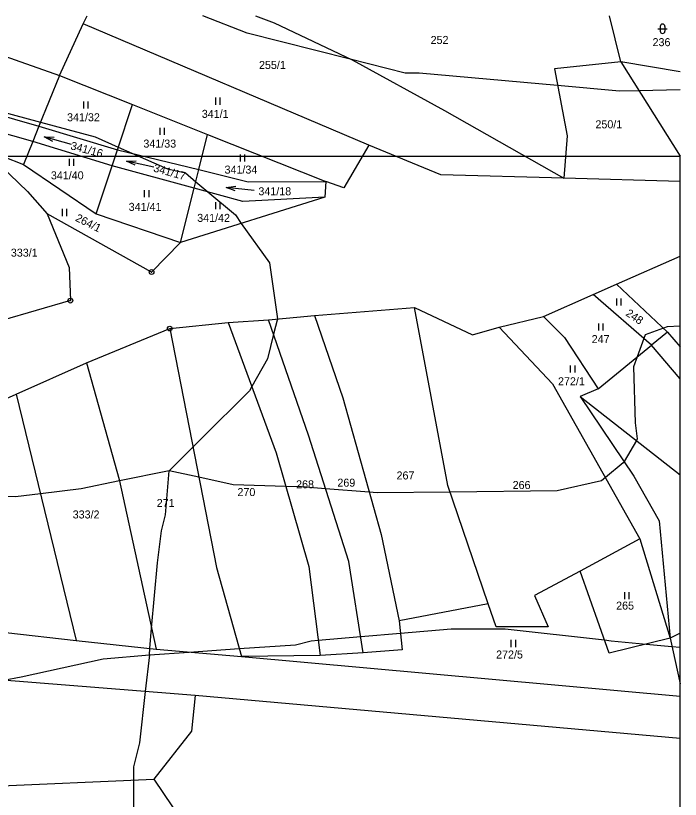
# Model space of a CAD drawing. Extents: x -756640 to -756220, y -1116060 to -1115741.
# Drawn here: x -756361.1 to -756220.1, y -1115907.5 to -1115741.2 of the extents above; entities that cross this region are included whole.
import ezdxf

# ---------------------------------------------------------------- set-up
doc = ezdxf.new("R2010")
doc.units = 0
for name, color, linetype in [('BPEJ', 7, 'Continuous'), ('Katastr_HRANICE DRÁHY', 7, 'Continuous'), ('Katastr_Hranice parcel', 7, 'Continuous'), ('Katastr_Parcelní čísla', 7, 'Continuous'), ('Katastr_Značky kultur', 7, 'Continuous')]:
    doc.layers.add(name, color=color, linetype=linetype)

msp = doc.modelspace()

# ---------------------------------------------------------------- linework, layer by layer
at = {"layer": 'BPEJ'}
for points in [[(-756220.13, -1115756.94), (-756228.88, -1115757.1), (-756233.07, -1115757.17), (-756246.16, -1115756), (-756275.51, -1115753.36), (-756278.48, -1115753.36), (-756290.19, -1115750.39), (-756312, -1115744.87), (-756321.46, -1115741.18)], [(-756364.61, -1115761.42), (-756355.88, -1115763.78), (-756344.25, -1115766.93), (-756339.39, -1115769.09), (-756336.47, -1115770.39), (-756328.97, -1115773.72), (-756325.15, -1115774.57), (-756322.94, -1115776.43), (-756320.41, -1115778.55), (-756314.54, -1115783.48), (-756313.28, -1115785.26), (-756307.33, -1115793.67), (-756305.63, -1115805.55), (-756306.45, -1115808.81), (-756307.75, -1115814.03), (-756311.06, -1115819.9), (-756311.57, -1115820.82), (-756321.76, -1115831.01), (-756323.53, -1115832.78), (-756328.55, -1115837.79)], [(-756220.13, -1115807.05), (-756222.89, -1115807.24), (-756223.7, -1115807.54), (-756227.56, -1115808.94)], [(-756227.56, -1115808.94), (-756227.86, -1115809.73), (-756229.3, -1115813.58), (-756230.1, -1115815.73), (-756229.68, -1115827.61), (-756229.26, -1115831.01), (-756229.45, -1115831.34), (-756232.07, -1115835.82), (-756232.23, -1115836.1), (-756236.03, -1115839.21), (-756236.89, -1115839.92), (-756246.23, -1115842.04), (-756268.99, -1115842.29), (-756284.42, -1115842.46), (-756286.13, -1115842.33), (-756295.38, -1115841.6), (-756300.54, -1115841.19), (-756303.81, -1115841.09), (-756314.97, -1115840.77), (-756322.27, -1115839.17), (-756328.55, -1115837.79)], [(-756328.55, -1115837.79), (-756339.1, -1115839.95), (-756347.22, -1115841.61), (-756355.89, -1115842.66)], [(-756332.79, -1115876.83), (-756332.67, -1115875.5), (-756332.3, -1115871.2), (-756331.09, -1115857.31), (-756330.24, -1115850.52), (-756329.39, -1115847.13), (-756328.55, -1115837.79)], [(-756355.89, -1115842.66), (-756361.22, -1115843.31), (-756373.35, -1115843.11), (-756382.69, -1115842.96), (-756387.1, -1115842.89), (-756391.28, -1115843.07), (-756402.93, -1115843.59), (-756415.53, -1115844.16), (-756432.93, -1115845.86), (-756441.01, -1115847.26), (-756445.2, -1115847.98), (-756454.99, -1115849.67), (-756461.04, -1115851.77), (-756475.79, -1115856.89), (-756487.39, -1115864.74), (-756490.21, -1115866.65), (-756491.4, -1115867.93), (-756498.24, -1115875.3), (-756501.24, -1115878.53)], [(-756332.79, -1115876.83), (-756324.36, -1115876.25), (-756313.7, -1115875.52), (-756301.81, -1115874.71), (-756298.42, -1115873.86), (-756296.98, -1115873.74), (-756287.94, -1115872.96), (-756279.52, -1115872.24), (-756268.72, -1115871.32), (-756257.26, -1115871.32), (-756236.21, -1115873.7), (-756234.77, -1115873.86), (-756227.37, -1115874.56), (-756221.9, -1115875.07), (-756220.13, -1115875.24)], [(-756444.19, -1115908.63), (-756440.57, -1115904.84), (-756435.47, -1115900.17), (-756422.74, -1115893.8), (-756411.29, -1115892.11), (-756409.41, -1115891.6), (-756400.26, -1115889.14), (-756381.59, -1115885.74), (-756363.76, -1115882.25), (-756359.95, -1115881.5), (-756342.55, -1115877.68), (-756332.79, -1115876.83)], [(-756332.79, -1115876.83), (-756333.68, -1115884.64), (-756334.91, -1115895.5), (-756336.18, -1115900.59), (-756336.18, -1115903.45), (-756336.18, -1115910.78), (-756335.33, -1115912.48), (-756335.76, -1115917.57), (-756331.52, -1115931.14), (-756325.58, -1115939.63), (-756314.15, -1115948.84), (-756302.4, -1115958.32), (-756299.27, -1115960.85)]]:
    msp.add_lwpolyline(points, dxfattribs=at)
at = {"layer": 'Defpoints'}
for p in [(-756640.13, -1115771.02), (-756220.13, -1116060.02)]:
    msp.add_line(p, (-756220.13, -1115771.02), dxfattribs=at)
at = {"layer": 'Katastr_HRANICE DRÁHY'}
for points in [[(-756286.21, -1115768.68), (-756291.51, -1115777.69)], [(-756270.95, -1115774.94), (-756286.21, -1115768.68)], [(-756244.82, -1115775.67), (-756270.95, -1115774.94)], [(-756295.36, -1115776.36), (-756295.53, -1115779.71)], [(-756291.51, -1115777.69), (-756295.36, -1115776.36)], [(-756220.13, -1115776.36), (-756244.82, -1115775.67)], [(-756295.53, -1115779.71), (-756326.15, -1115789.29)], [(-756332.32, -1115795.59), (-756354.5, -1115783.25)], [(-756354.5, -1115783.25), (-756349.78, -1115794.61)], [(-756326.15, -1115789.29), (-756332.32, -1115795.59)], [(-756233.67, -1115798.18), (-756220.13, -1115792.24)], [(-756349.78, -1115794.61), (-756349.55, -1115801.67)], [(-756238.65, -1115800.38), (-756233.67, -1115798.18)], [(-756349.55, -1115801.67), (-756364.06, -1115805.89)], [(-756249.19, -1115805.03), (-756238.65, -1115800.38)], [(-756297.75, -1115804.84), (-756276.55, -1115803.13)], [(-756276.55, -1115803.13), (-756264.22, -1115808.93)], [(-756307.52, -1115805.72), (-756297.75, -1115804.84)], [(-756258.54, -1115807.32), (-756249.19, -1115805.03)], [(-756328.46, -1115807.61), (-756316.08, -1115806.33)], [(-756316.08, -1115806.33), (-756307.52, -1115805.72)], [(-756346.1, -1115814.88), (-756328.46, -1115807.61)], [(-756264.22, -1115808.93), (-756258.54, -1115807.32)], [(-756361.05, -1115821.51), (-756346.1, -1115814.88)], [(-756376.92, -1115828.62), (-756361.05, -1115821.51)]]:
    msp.add_lwpolyline(points, dxfattribs=at)
at = {"layer": 'Katastr_Hranice parcel'}
for points in [[(-756346.83, -1115742.94), (-756346.01, -1115741.18)], [(-756310.26, -1115741.18), (-756306.31, -1115742.72)], [(-756232.74, -1115750.96), (-756235.15, -1115741.18)], [(-756351.86, -1115753.85), (-756346.83, -1115742.94)], [(-756286.21, -1115768.68), (-756346.83, -1115742.94)], [(-756306.31, -1115742.72), (-756289.79, -1115750.58)], [(-756370.72, -1115747.22), (-756351.86, -1115753.85)], [(-756289.79, -1115750.58), (-756270.17, -1115761.29)], [(-756232.74, -1115750.96), (-756246.82, -1115752.43)], [(-756220.13, -1115753.07), (-756232.74, -1115750.96)], [(-756232.74, -1115750.96), (-756220.13, -1115771.02)], [(-756246.82, -1115752.43), (-756244.17, -1115766.71)], [(-756351.86, -1115753.85), (-756356.23, -1115764.66)], [(-756351.86, -1115753.85), (-756336.39, -1115760)], [(-756382.59, -1115757.09), (-756356.23, -1115764.66)], [(-756339.57, -1115769.63), (-756336.39, -1115760)], [(-756336.39, -1115760), (-756320.43, -1115766.37)], [(-756357.53, -1115767.92), (-756383.55, -1115760.55)], [(-756270.17, -1115761.29), (-756244.82, -1115775.67)], [(-756356.23, -1115764.66), (-756357.53, -1115767.92)], [(-756356.23, -1115764.66), (-756339.57, -1115769.63)], [(-756322.3, -1115773.86), (-756320.43, -1115766.37)], [(-756320.43, -1115766.37), (-756295.36, -1115776.36)], [(-756244.17, -1115766.71), (-756244.82, -1115775.67)], [(-756357.53, -1115767.92), (-756359.47, -1115772.77)], [(-756340.69, -1115773.02), (-756357.53, -1115767.92)], [(-756368.19, -1115769.4), (-756358.61, -1115778.51)], [(-756368.19, -1115769.4), (-756359.47, -1115772.77)], [(-756340.69, -1115773.02), (-756339.57, -1115769.63)], [(-756339.57, -1115769.63), (-756322.3, -1115773.86)], [(-756359.47, -1115772.77), (-756344.08, -1115783.27)], [(-756344.08, -1115783.27), (-756340.69, -1115773.02)], [(-756323.28, -1115777.77), (-756340.69, -1115773.02)], [(-756323.28, -1115777.77), (-756322.3, -1115773.86)], [(-756322.3, -1115773.86), (-756311.8, -1115776.44)], [(-756311.8, -1115776.44), (-756295.36, -1115776.36)], [(-756326.15, -1115789.29), (-756323.28, -1115777.77)], [(-756312.92, -1115780.6), (-756323.28, -1115777.77)], [(-756358.61, -1115778.51), (-756354.5, -1115783.25)], [(-756295.53, -1115779.71), (-756312.92, -1115780.6)], [(-756344.08, -1115783.27), (-756326.15, -1115789.29)], [(-756233.67, -1115798.18), (-756222.85, -1115808.34)], [(-756226.28, -1115811.1), (-756238.65, -1115800.38)], [(-756269.47, -1115840.87), (-756276.55, -1115803.13)], [(-756297.75, -1115804.84), (-756291.76, -1115822.27)], [(-756249.19, -1115805.03), (-756244.72, -1115809.5)], [(-756316.08, -1115806.33), (-756305.85, -1115833.96)], [(-756299.01, -1115830.2), (-756307.52, -1115805.72)], [(-756328.46, -1115807.61), (-756318.52, -1115858.32)], [(-756258.54, -1115807.32), (-756247.22, -1115819.31)], [(-756222.85, -1115808.34), (-756226.28, -1115811.1)], [(-756222.85, -1115808.34), (-756220.13, -1115811.48)], [(-756244.72, -1115809.5), (-756237.54, -1115820.36)], [(-756237.54, -1115820.36), (-756226.28, -1115811.1)], [(-756220.13, -1115818.25), (-756226.28, -1115811.1)], [(-756346.1, -1115814.88), (-756339.17, -1115839.64)], [(-756247.22, -1115819.31), (-756228.69, -1115852.25)], [(-756361.05, -1115821.51), (-756348.29, -1115873.78)], [(-756237.54, -1115820.36), (-756241.38, -1115822.04)], [(-756291.76, -1115822.27), (-756283.6, -1115851.33)], [(-756241.38, -1115822.04), (-756229.98, -1115838.91)], [(-756241.38, -1115822.04), (-756220.13, -1115838.61)], [(-756290.46, -1115857.06), (-756299.01, -1115830.2)], [(-756305.85, -1115833.96), (-756298.96, -1115858.11)], [(-756339.17, -1115839.64), (-756331.33, -1115875.65)], [(-756229.98, -1115838.91), (-756224.63, -1115848.41)], [(-756260.9, -1115866), (-756269.47, -1115840.87)], [(-756224.63, -1115848.41), (-756222.3, -1115873.3)], [(-756283.6, -1115851.33), (-756279.8, -1115869.62)], [(-756228.69, -1115852.25), (-756241.41, -1115859.07)], [(-756228.69, -1115852.25), (-756222.3, -1115873.3)], [(-756318.52, -1115858.32), (-756313.23, -1115877.22)], [(-756298.96, -1115858.11), (-756296.57, -1115876.96)], [(-756287.4, -1115876.41), (-756290.46, -1115857.06)], [(-756241.41, -1115859.07), (-756251.09, -1115864.26)], [(-756235.22, -1115876.5), (-756241.41, -1115859.07)], [(-756251.09, -1115864.26), (-756248.17, -1115870.94)], [(-756260.9, -1115866), (-756279.8, -1115869.62)], [(-756259.21, -1115870.94), (-756260.9, -1115866)], [(-756279.8, -1115869.62), (-756279.14, -1115875.81)], [(-756248.17, -1115870.94), (-756259.21, -1115870.94)], [(-756363.21, -1115872.14), (-756348.29, -1115873.78)], [(-756220.13, -1115872.23), (-756222.3, -1115873.3)], [(-756348.29, -1115873.78), (-756331.33, -1115875.65)], [(-756222.3, -1115873.3), (-756235.22, -1115876.5)], [(-756222.3, -1115873.3), (-756220.13, -1115882.98)], [(-756331.33, -1115875.65), (-756313.23, -1115877.22)], [(-756287.4, -1115876.41), (-756296.57, -1115876.96)], [(-756279.14, -1115875.81), (-756287.4, -1115876.41)], [(-756323.04, -1115885.48), (-756423.52, -1115877.5)], [(-756296.57, -1115876.96), (-756313.23, -1115877.22)], [(-756313.23, -1115877.22), (-756220.13, -1115885.65)], [(-756323.04, -1115885.48), (-756323.86, -1115893.05)], [(-756220.13, -1115894.6), (-756323.04, -1115885.48)], [(-756323.86, -1115893.05), (-756331.81, -1115903.26)], [(-756367.5, -1115904.78), (-756331.81, -1115903.26)], [(-756331.81, -1115903.26), (-756325.96, -1115911.91)]]:
    msp.add_lwpolyline(points, dxfattribs=at)
at = {"layer": 'Katastr_Značky kultur'}
for p, q in [((-756224.41, -1115743.46), (-756224.41, -1115744.46)), ((-756223.41, -1115743.46), (-756223.41, -1115744.46)), ((-756224.91, -1115743.96), (-756222.91, -1115743.96)), ((-756346.74, -1115759.39), (-756346.74, -1115760.89)), ((-756345.74, -1115760.89), (-756345.74, -1115759.39)), ((-756318.75, -1115758.58), (-756318.75, -1115760.08)), ((-756317.75, -1115760.08), (-756317.75, -1115758.58)), ((-756330.55, -1115764.98), (-756330.55, -1115766.48)), ((-756329.55, -1115766.48), (-756329.55, -1115764.98)), ((-756349.31, -1115768.55), (-756355.07, -1115766.87)), ((-756349.82, -1115771.55), (-756349.82, -1115773.05)), ((-756348.82, -1115773.05), (-756348.82, -1115771.55)), ((-756313.5, -1115770.64), (-756313.5, -1115772.14)), ((-756312.5, -1115772.14), (-756312.5, -1115770.64)), ((-756331.81, -1115773.31), (-756337.67, -1115772.03)), ((-756333.86, -1115778.19), (-756333.86, -1115779.69)), ((-756332.86, -1115779.69), (-756332.86, -1115778.19)), ((-756310.52, -1115778.31), (-756316.48, -1115777.67)), ((-756318.77, -1115780.76), (-756318.77, -1115782.26)), ((-756317.77, -1115782.26), (-756317.77, -1115780.76)), ((-756351.31, -1115782.21), (-756351.31, -1115783.71)), ((-756350.31, -1115783.71), (-756350.31, -1115782.21)), ((-756332.37, -1115795.59), (-756332.27, -1115795.59)), ((-756349.6, -1115801.67), (-756349.5, -1115801.67)), ((-756233.65, -1115801.2), (-756233.65, -1115802.7)), ((-756232.65, -1115802.7), (-756232.65, -1115801.2)), ((-756237.51, -1115806.49), (-756237.51, -1115807.99)), ((-756236.51, -1115807.99), (-756236.51, -1115806.49)), ((-756328.51, -1115807.61), (-756328.41, -1115807.61)), ((-756243.47, -1115815.43), (-756243.47, -1115816.93)), ((-756242.47, -1115816.93), (-756242.47, -1115815.43)), ((-756231.99, -1115863.54), (-756231.99, -1115865.04)), ((-756230.99, -1115865.04), (-756230.99, -1115863.54)), ((-756256.06, -1115873.7), (-756256.06, -1115875.2)), ((-756255.06, -1115875.2), (-756255.06, -1115873.7))]:
    msp.add_line(p, q, dxfattribs=at)
for points in [[(-756353.29, -1115767.91), (-756355.07, -1115766.87), (-756353.01, -1115766.95)], [(-756335.82, -1115772.94), (-756337.67, -1115772.03), (-756335.61, -1115771.97)], [(-756314.55, -1115778.38), (-756316.48, -1115777.67), (-756314.44, -1115777.39)]]:
    msp.add_lwpolyline(points, dxfattribs=at)
for centre in [(-756332.32, -1115795.59), (-756349.55, -1115801.67), (-756328.46, -1115807.61)]:
    msp.add_circle(centre, 0.499, dxfattribs=at)
for centre, start, end in [((-756223.91, -1115743.46), 0, 180), ((-756223.91, -1115744.46), 180, 0)]:
    msp.add_arc(centre, 0.5, start, end, dxfattribs=at)

# ---------------------------------------------------------------- texts
at = {"layer": 'Katastr_Parcelní čísla'}
for s, p in [('252', (-756273.11, -1115747.18)), ('236', (-756226.02, -1115747.65)), ('255/1', (-756309.52, -1115752.49)), ('341/32', (-756350.24, -1115763.59)), ('341/1', (-756321.66, -1115762.87)), ('250/1', (-756238.14, -1115765.09)), ('341/33', (-756334.05, -1115769.18)), ('341/34', (-756316.83, -1115774.7)), ('341/40', (-756353.68, -1115775.92)), ('341/18', (-756309.65, -1115779.3)), ('341/41', (-756337.17, -1115782.61)), ('341/42', (-756322.63, -1115784.95)), ('333/1', (-756362.17, -1115792.33)), ('247', (-756238.94, -1115810.69)), ('272/1', (-756246.08, -1115819.63)), ('267', (-756280.34, -1115839.62)), ('268', (-756301.65, -1115841.5)), ('269', (-756292.89, -1115841.16)), ('266', (-756255.71, -1115841.65)), ('270', (-756314.09, -1115843.15)), ('271', (-756331.22, -1115845.47)), ('333/2', (-756349.05, -1115847.9)), ('265', (-756233.75, -1115867.25)), ('272/5', (-756259.22, -1115877.63))]:
    msp.add_text(s, height=1.7, dxfattribs=at).set_placement(p)
for s, rotation, p in [('341/16', 344.9425, (-756349.63, -1115769.51)), ('341/17', 344.3999, (-756332.04, -1115774.23)), ('264/1', 333.387, (-756348.64, -1115784.66)), ('248', 326.078, (-756231.87, -1115804.72))]:
    msp.add_text(s, height=1.7, rotation=rotation, dxfattribs=at).set_placement(p)

doc.saveas('drawing.dxf')
